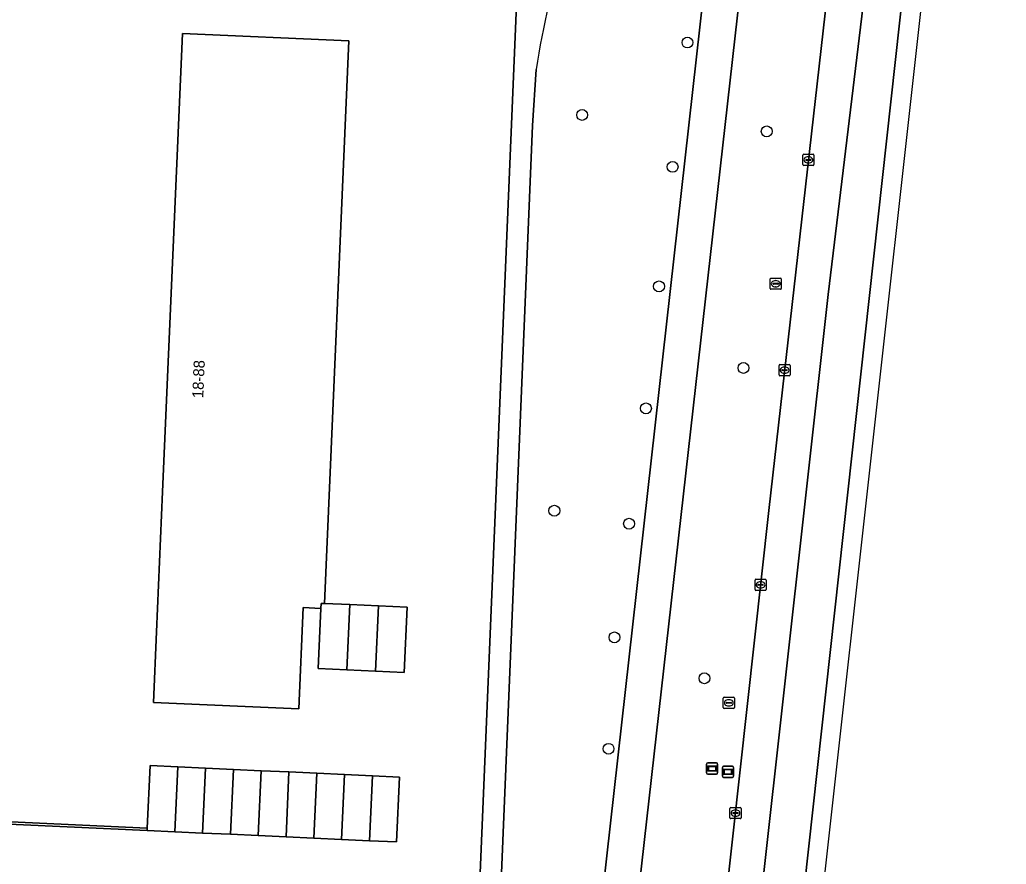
# Model space of a CAD drawing. Extents: x 161354 to 162026, y 386504 to 387460.
# Drawn here: x 161895 to 161983.7, y 386903.7 to 386979.6 of the extents above; entities that cross this region are included whole.
import ezdxf

# ---------------------------------------------------------------- set-up
doc = ezdxf.new("R2010")
doc.units = 0
for name, color, linetype in [('IMGEO_Berm_groen', 7, 'Continuous'), ('IMGEO_Boom', 7, 'Continuous'), ('IMGEO_Erf', 7, 'Continuous'), ('IMGEO_Fietspad_gesloten', 7, 'Continuous'), ('IMGEO_Kolk', 7, 'Continuous'), ('IMGEO_Loofbos', 7, 'Continuous'), ('IMGEO_Muur', 7, 'Continuous'), ('IMGEO_Pand', 7, 'Continuous'), ('IMGEO_Pand_nummerreeks', 7, 'Continuous'), ('IMGEO_Rijbaan_regionaal_gesloten', 7, 'Continuous'), ('IMGEO_Rioolput', 7, 'Continuous'), ('IMGEO_Voetpad_halfverhard', 7, 'Continuous'), ('IMGEO_Wegwijzer', 7, 'Continuous')]:
    doc.layers.add(name, color=color, linetype=linetype)

msp = doc.modelspace()

# ---------------------------------------------------------------- linework, layer by layer
at = {"layer": 'IMGEO_Berm_groen'}
for points in [[(161967.257, 387050.915), (161961.639, 387000), (161960.38, 386987.709), (161938.796, 386796.287), (161936.822, 386778.776), (161933.448, 386750), (161933.024, 386747.211), (161931.111, 386738.486), (161920.088, 386699.556), (161913.466, 386677.408), (161909.577, 386666.417)], [(161931.854, 386730.957), (161936.419, 386750), (161939.69, 386764.511), (161941.551, 386773.496), (161945.484, 386795.546), (161945.681, 386796.648), (161949.337, 386819.995), (161954.584, 386865.29), (161962.329, 386935.471), (161969.651, 387000), (161975.237, 387050.12)]]:
    msp.add_lwpolyline(points, dxfattribs=at)
at = {"layer": 'IMGEO_Boom'}
for centre in [(161955.019, 386977.518), (161945.55, 386971.009), (161962.142, 386969.533), (161953.686, 386966.346), (161952.46, 386955.604), (161960.052, 386948.28), (161951.282, 386944.646), (161943.052, 386935.456), (161949.767, 386934.285), (161948.456, 386924.068), (161956.544, 386920.397), (161947.924, 386914.063)]:
    msp.add_circle(centre, 0.489, dxfattribs=at)
at = {"layer": 'IMGEO_Erf'}
for points in [[(161885.264, 386901.684), (161936.238, 386899.338), (161940.02, 386989.533), (161894.944, 386991.428)], [(161891.578, 386907.611), (161906.455, 386906.926), (161906.714, 386912.556), (161909.211, 386912.441), (161911.709, 386912.326), (161914.206, 386912.211), (161916.703, 386912.097), (161919.201, 386911.982), (161921.698, 386911.867), (161924.196, 386911.752), (161926.693, 386911.638), (161929.146, 386911.525), (161928.878, 386905.694), (161926.425, 386905.807), (161923.928, 386905.922), (161921.43, 386906.037), (161918.933, 386906.152), (161916.435, 386906.267), (161913.938, 386906.382), (161911.441, 386906.496), (161908.943, 386906.611), (161906.446, 386906.726), (161891.37, 386907.42)]]:
    msp.add_lwpolyline(points, dxfattribs=at)
msp.add_lwpolyline([(161924.585, 386977.677), (161922.388, 386927.113), (161924.662, 386927.014), (161927.238, 386926.902), (161929.812, 386926.79), (161929.558, 386920.928), (161926.983, 386921.04), (161924.407, 386921.152), (161921.832, 386921.264), (161922.067, 386926.675), (161920.488, 386926.744), (161920.093, 386917.65), (161907.022, 386918.218), (161907.298, 386924.565), (161907.845, 386937.154), (161909.635, 386978.326)], close=True, dxfattribs=at)
at = {"layer": 'IMGEO_Fietspad_gesloten'}
for points in [[(161964.191, 387051.221), (161958.492, 387000), (161935.661, 386796.635)], [(161938.796, 386796.287), (161960.38, 386987.709), (161961.639, 387000), (161967.257, 387050.915)]]:
    msp.add_lwpolyline(points, dxfattribs=at)
at = {"layer": 'IMGEO_Kolk'}
for p, q in [((161965.388, 386966.547), (161965.388, 386967.399)), ((161965.463, 386967.473), (161966.315, 386967.473)), ((161966.389, 386967.399), (161966.389, 386966.547)), ((161966.315, 386966.473), (161965.463, 386966.473)), ((161965.647, 386966.967), (161965.647, 386966.979)), ((161966.085, 386966.93), (161965.687, 386966.93)), ((161965.69, 386967.016), (161966.088, 386967.016)), ((161965.899, 386966.693), (161965.874, 386966.693)), ((161965.876, 386967.253), (161965.901, 386967.253)), ((161966.131, 386966.979), (161966.131, 386966.967)), ((161963.246, 386947.653), (161963.246, 386948.505)), ((161963.321, 386948.579), (161964.173, 386948.579)), ((161963.505, 386948.073), (161963.505, 386948.085)), ((161963.943, 386948.036), (161963.545, 386948.036)), ((161963.548, 386948.122), (161963.946, 386948.122)), ((161963.734, 386948.359), (161963.759, 386948.359)), ((161963.989, 386948.085), (161963.989, 386948.073)), ((161964.247, 386948.505), (161964.247, 386947.653)), ((161964.173, 386947.579), (161963.321, 386947.579)), ((161963.757, 386947.799), (161963.732, 386947.799)), ((161961.094, 386928.366), (161961.094, 386929.218)), ((161961.169, 386929.292), (161962.021, 386929.292)), ((161962.095, 386929.218), (161962.095, 386928.366)), ((161961.353, 386928.786), (161961.353, 386928.798)), ((161961.791, 386928.749), (161961.393, 386928.749)), ((161961.396, 386928.835), (161961.794, 386928.835)), ((161961.605, 386928.512), (161961.58, 386928.512)), ((161961.582, 386929.072), (161961.607, 386929.072)), ((161961.837, 386928.798), (161961.837, 386928.786)), ((161962.021, 386928.292), (161961.169, 386928.292)), ((161958.911, 386908.786), (161959.763, 386908.786)), ((161958.836, 386907.86), (161958.836, 386908.712)), ((161959.095, 386908.28), (161959.095, 386908.292)), ((161959.533, 386908.243), (161959.135, 386908.243)), ((161959.138, 386908.329), (161959.536, 386908.329)), ((161959.347, 386908.006), (161959.322, 386908.006)), ((161959.324, 386908.566), (161959.349, 386908.566)), ((161959.579, 386908.292), (161959.579, 386908.28)), ((161959.837, 386908.712), (161959.837, 386907.86)), ((161959.763, 386907.786), (161958.911, 386907.786))]:
    msp.add_line(p, q, dxfattribs=at)
for points in [[(161965.388, 386966.547), (161965.388, 386967.399)], [(161965.463, 386967.473), (161966.315, 386967.473)], [(161966.389, 386967.399), (161966.389, 386966.547)], [(161966.315, 386966.473), (161965.463, 386966.473)], [(161963.246, 386947.653), (161963.246, 386948.505)], [(161963.321, 386948.579), (161964.173, 386948.579)], [(161964.247, 386948.505), (161964.247, 386947.653)], [(161964.173, 386947.579), (161963.321, 386947.579)], [(161961.094, 386928.366), (161961.094, 386929.218)], [(161961.169, 386929.292), (161962.021, 386929.292)], [(161962.095, 386929.218), (161962.095, 386928.366)], [(161962.021, 386928.292), (161961.169, 386928.292)], [(161958.911, 386908.786), (161959.763, 386908.786)], [(161958.836, 386907.86), (161958.836, 386908.712)], [(161959.837, 386908.712), (161959.837, 386907.86)], [(161959.763, 386907.786), (161958.911, 386907.786)]]:
    msp.add_lwpolyline(points, dxfattribs=at)
for centre, radius, start, end in [((161965.465, 386967.397), 0.0765, 91.55205, 178.44795), ((161965.465, 386967.397), 0.0765, 91.55205, 178.44795), ((161966.313, 386967.397), 0.0765, 1.55205, 88.44795), ((161966.313, 386967.397), 0.0765, 1.55205, 88.44795), ((161965.465, 386966.549), 0.0765, 181.55205, 268.44795), ((161965.465, 386966.549), 0.0765, 181.55205, 268.44795), ((161965.687, 386966.976), 0.0403, 85.87752, 175.75265), ((161965.684, 386966.966), 0.0366, 178.93798, 274.71019), ((161966.088, 386966.973), 0.043, 264.86636, 352.45326), ((161966.092, 386966.978), 0.0386, 1.73085, 96.63898), ((161966.313, 386966.549), 0.0765, 271.55205, 358.44795), ((161966.313, 386966.549), 0.0765, 271.55205, 358.44795), ((161963.323, 386948.503), 0.0765, 91.55205, 178.44795), ((161963.323, 386948.503), 0.0765, 91.55205, 178.44795), ((161963.545, 386948.082), 0.0403, 85.87752, 175.75265), ((161963.542, 386948.072), 0.0366, 178.93798, 274.71019), ((161963.946, 386948.079), 0.043, 264.86636, 352.45326), ((161963.95, 386948.084), 0.0386, 1.73085, 96.63898), ((161964.171, 386948.503), 0.0765, 1.55205, 88.44795), ((161964.171, 386948.503), 0.0765, 1.55205, 88.44795), ((161963.323, 386947.655), 0.0765, 181.55205, 268.44795), ((161963.323, 386947.655), 0.0765, 181.55205, 268.44795), ((161964.171, 386947.655), 0.0765, 271.55205, 358.44795), ((161964.171, 386947.655), 0.0765, 271.55205, 358.44795), ((161961.171, 386929.216), 0.0765, 91.55205, 178.44795), ((161961.171, 386929.216), 0.0765, 91.55205, 178.44795), ((161962.019, 386929.216), 0.0765, 1.55205, 88.44795), ((161962.019, 386929.216), 0.0765, 1.55205, 88.44795), ((161961.171, 386928.368), 0.0765, 181.55205, 268.44795), ((161961.171, 386928.368), 0.0765, 181.55205, 268.44795), ((161961.393, 386928.795), 0.0403, 85.87752, 175.75265), ((161961.39, 386928.785), 0.0366, 178.93798, 274.71019), ((161961.794, 386928.792), 0.043, 264.86636, 352.45326), ((161961.798, 386928.797), 0.0386, 1.73085, 96.63898), ((161962.019, 386928.368), 0.0765, 271.55205, 358.44795), ((161962.019, 386928.368), 0.0765, 271.55205, 358.44795), ((161958.913, 386908.71), 0.0765, 91.55205, 178.44795), ((161958.913, 386908.71), 0.0765, 91.55205, 178.44795), ((161959.761, 386908.71), 0.0765, 1.55205, 88.44795), ((161959.761, 386908.71), 0.0765, 1.55205, 88.44795), ((161959.135, 386908.289), 0.0403, 85.87752, 175.75265), ((161959.132, 386908.279), 0.0366, 178.93798, 274.71019), ((161959.536, 386908.286), 0.043, 264.86636, 352.45326), ((161959.54, 386908.291), 0.0386, 1.73085, 96.63898), ((161958.913, 386907.862), 0.0765, 181.55205, 268.44795), ((161958.913, 386907.862), 0.0765, 181.55205, 268.44795), ((161959.761, 386907.862), 0.0765, 271.55205, 358.44795), ((161959.761, 386907.862), 0.0765, 271.55205, 358.44795)]:
    msp.add_arc(centre, radius, start, end, dxfattribs=at)
for centre, major_axis, ratio, start_param, end_param in [((161965.875, 386966.973), (-0.387, 0.002), 0.722429, 4.712389, 7.853982), ((161965.9, 386966.973), (-0.39, 0.002), 0.717154, 1.570796, 4.712389), ((161963.733, 386948.079), (-0.387, 0.002), 0.722429, 4.712389, 7.853982), ((161963.758, 386948.079), (-0.39, 0.002), 0.717154, 1.570796, 4.712389), ((161961.581, 386928.792), (-0.387, 0.002), 0.722429, 4.712389, 7.853982), ((161961.606, 386928.792), (-0.39, 0.002), 0.717154, 1.570796, 4.712389), ((161959.323, 386908.286), (-0.387, 0.002), 0.722429, 4.712389, 7.853982), ((161959.348, 386908.286), (-0.39, 0.002), 0.717154, 1.570796, 4.712389)]:
    msp.add_ellipse(centre, major_axis=major_axis, ratio=ratio, start_param=start_param, end_param=end_param, dxfattribs=at)
at = {"layer": 'IMGEO_Loofbos'}
for points in [[(161913.776, 386748.036), (161911.767, 386689.472), (161913.777, 386689.388), (161921.99, 386717.644), (161927.704, 386738.292), (161930.041, 386748.73), (161930.197, 386750), (161932.945, 386772.439), (161935.661, 386796.635), (161958.492, 387000)], [(161941.407, 386975.097), (161941.082, 386970.072), (161938.146, 386899.309), (161937.723, 386895.33)]]:
    msp.add_lwpolyline(points, dxfattribs=at)
msp.add_arc((162043.236, 386958.619), 103.153, 157.58635, 170.80783, dxfattribs=at)
at = {"layer": 'IMGEO_Muur'}
msp.add_lwpolyline([(161891.965, 386921.204), (161891.37, 386907.42), (161906.446, 386906.726), (161906.455, 386906.926), (161891.578, 386907.611), (161892.338, 386925.195), (161892.138, 386925.204)], close=True, dxfattribs=at)
at = {"layer": 'IMGEO_Pand'}
for points in [[(161907.022, 386918.218), (161920.093, 386917.65), (161920.488, 386926.744), (161922.067, 386926.675), (161922.085, 386927.13), (161922.388, 386927.113), (161924.585, 386977.677), (161909.635, 386978.326), (161907.845, 386937.154), (161907.298, 386924.565)], [(161924.662, 386927.014), (161922.388, 386927.113), (161922.085, 386927.13), (161922.067, 386926.675), (161921.832, 386921.264), (161924.407, 386921.152)], [(161927.238, 386926.902), (161924.662, 386927.014), (161924.407, 386921.152), (161926.983, 386921.04)], [(161926.983, 386921.04), (161929.558, 386920.928), (161929.812, 386926.79), (161927.238, 386926.902)], [(161909.211, 386912.441), (161906.714, 386912.556), (161906.455, 386906.926), (161906.446, 386906.726), (161908.943, 386906.611)], [(161911.709, 386912.326), (161909.211, 386912.441), (161908.943, 386906.611), (161911.441, 386906.496)], [(161914.206, 386912.211), (161911.709, 386912.326), (161911.441, 386906.496), (161913.938, 386906.382)], [(161916.703, 386912.097), (161914.206, 386912.211), (161913.938, 386906.382), (161916.435, 386906.267)], [(161919.201, 386911.982), (161916.703, 386912.097), (161916.435, 386906.267), (161918.933, 386906.152)], [(161921.698, 386911.867), (161919.201, 386911.982), (161918.933, 386906.152), (161921.43, 386906.037)], [(161924.196, 386911.752), (161921.698, 386911.867), (161921.43, 386906.037), (161923.928, 386905.922)], [(161926.693, 386911.638), (161924.196, 386911.752), (161923.928, 386905.922), (161926.425, 386905.807)], [(161929.146, 386911.525), (161926.693, 386911.638), (161926.425, 386905.807), (161928.878, 386905.694)]]:
    msp.add_lwpolyline(points, close=True, dxfattribs=at)
at = {"layer": 'IMGEO_Rijbaan_regionaal_gesloten'}
for points in [[(161953.318, 386794.679), (161962.379, 386873.244), (161976.049, 386997.238), (161981.984, 387049.448), (161978.469, 387049.798), (161974.354, 387011.236), (161973.137, 387000.209), (161967.661, 386954.866), (161949.872, 386795.06), (161946.557, 386765.215), (161942.589, 386729.489), (161942.439, 386728.019), (161926.424, 386570.316), (161923.246, 386535.823), (161922.934, 386532.145), (161926.119, 386532.024), (161929.934, 386573.912), (161932.687, 386601.55), (161933.498, 386609.431), (161933.982, 386612.625), (161940.783, 386677.087)], [(161978.469, 387049.798), (161975.237, 387050.12), (161969.651, 387000), (161962.329, 386935.471), (161954.584, 386865.29), (161949.337, 386819.995), (161945.681, 386796.648), (161945.484, 386795.546), (161946.236, 386795.463), (161949.151, 386795.14), (161949.872, 386795.06), (161967.661, 386954.866), (161973.137, 387000.209), (161974.354, 387011.236)], [(161928.749, 386531.924), (161935.094, 386600.16), (161938.388, 386635.586), (161940.62, 386659.585), (161959.612, 386832.977), (161983.673, 387049.28), (161981.984, 387049.448), (161976.049, 386997.238), (161962.379, 386873.244), (161953.318, 386794.679), (161940.783, 386677.087), (161933.982, 386612.625), (161933.498, 386609.431), (161932.687, 386601.55), (161929.934, 386573.912), (161926.119, 386532.024)]]:
    msp.add_lwpolyline(points, close=True, dxfattribs=at)
at = {"layer": 'IMGEO_Rioolput'}
for p, q in [((161962.449, 386955.422), (161962.449, 386956.274)), ((161962.524, 386956.348), (161963.376, 386956.348)), ((161962.708, 386955.842), (161962.708, 386955.854)), ((161963.146, 386955.805), (161962.748, 386955.805)), ((161962.751, 386955.891), (161963.149, 386955.891)), ((161962.937, 386956.128), (161962.962, 386956.128)), ((161963.192, 386955.854), (161963.192, 386955.842)), ((161963.45, 386956.274), (161963.45, 386955.422)), ((161963.376, 386955.348), (161962.524, 386955.348)), ((161962.96, 386955.568), (161962.935, 386955.568)), ((161958.235, 386917.767), (161958.235, 386918.619)), ((161958.31, 386918.693), (161959.162, 386918.693)), ((161959.236, 386918.619), (161959.236, 386917.767)), ((161959.162, 386917.693), (161958.31, 386917.693)), ((161958.494, 386918.187), (161958.494, 386918.199)), ((161958.932, 386918.15), (161958.534, 386918.15)), ((161958.537, 386918.236), (161958.935, 386918.236)), ((161958.746, 386917.913), (161958.721, 386917.913)), ((161958.723, 386918.473), (161958.748, 386918.473)), ((161958.978, 386918.199), (161958.978, 386918.187))]:
    msp.add_line(p, q, dxfattribs=at)
for points in [[(161962.449, 386955.422), (161962.449, 386956.274)], [(161962.524, 386956.348), (161963.376, 386956.348)], [(161963.45, 386956.274), (161963.45, 386955.422)], [(161963.376, 386955.348), (161962.524, 386955.348)], [(161958.235, 386917.767), (161958.235, 386918.619)], [(161958.31, 386918.693), (161959.162, 386918.693)], [(161959.236, 386918.619), (161959.236, 386917.767)], [(161959.162, 386917.693), (161958.31, 386917.693)]]:
    msp.add_lwpolyline(points, dxfattribs=at)
for centre, radius, start, end in [((161962.526, 386956.272), 0.0765, 91.55205, 178.44795), ((161962.526, 386956.272), 0.0765, 91.55205, 178.44795), ((161962.748, 386955.851), 0.0403, 85.87752, 175.75265), ((161962.745, 386955.841), 0.0366, 178.93798, 274.71019), ((161963.149, 386955.848), 0.043, 264.86636, 352.45326), ((161963.153, 386955.853), 0.0386, 1.73085, 96.63898), ((161963.374, 386956.272), 0.0765, 1.55205, 88.44795), ((161963.374, 386956.272), 0.0765, 1.55205, 88.44795), ((161962.526, 386955.424), 0.0765, 181.55205, 268.44795), ((161962.526, 386955.424), 0.0765, 181.55205, 268.44795), ((161963.374, 386955.424), 0.0765, 271.55205, 358.44795), ((161963.374, 386955.424), 0.0765, 271.55205, 358.44795), ((161958.312, 386918.617), 0.0765, 91.55205, 178.44795), ((161958.312, 386918.617), 0.0765, 91.55205, 178.44795), ((161959.16, 386918.617), 0.0765, 1.55205, 88.44795), ((161959.16, 386918.617), 0.0765, 1.55205, 88.44795), ((161958.312, 386917.769), 0.0765, 181.55205, 268.44795), ((161958.312, 386917.769), 0.0765, 181.55205, 268.44795), ((161958.534, 386918.196), 0.0403, 85.87752, 175.75265), ((161958.531, 386918.186), 0.0366, 178.93798, 274.71019), ((161958.935, 386918.193), 0.043, 264.86636, 352.45326), ((161958.939, 386918.198), 0.0386, 1.73085, 96.63898), ((161959.16, 386917.769), 0.0765, 271.55205, 358.44795), ((161959.16, 386917.769), 0.0765, 271.55205, 358.44795)]:
    msp.add_arc(centre, radius, start, end, dxfattribs=at)
for centre, major_axis, ratio, start_param, end_param in [((161962.936, 386955.848), (-0.387, 0.002), 0.722429, 4.712389, 7.853982), ((161962.961, 386955.848), (-0.39, 0.002), 0.717154, 1.570796, 4.712389), ((161958.722, 386918.193), (-0.387, 0.002), 0.722429, 4.712389, 7.853982), ((161958.747, 386918.193), (-0.39, 0.002), 0.717154, 1.570796, 4.712389)]:
    msp.add_ellipse(centre, major_axis=major_axis, ratio=ratio, start_param=start_param, end_param=end_param, dxfattribs=at)
at = {"layer": 'IMGEO_Voetpad_halfverhard'}
for points in [[(161949.829, 387052.652), (161948.584, 387020.063), (161948.284, 387012.203), (161947.779, 387006.274), (161946.435, 387000), (161946.053, 386998.219), (161946.029, 386998.119), (161945.843, 386997.496), (161945.603, 386996.892), (161945.309, 386996.312), (161944.965, 386995.76), (161944.573, 386995.242), (161944.136, 386994.761), (161943.658, 386994.32), (161943.143, 386993.924), (161942.594, 386993.576), (161942.016, 386993.278), (161941.414, 386993.033), (161940.793, 386992.842), (161940.157, 386992.708), (161940.02, 386989.533), (161936.238, 386899.338)], [(161941.082, 386970.072), (161941.407, 386975.097)], [(161937.723, 386895.33), (161938.146, 386899.309), (161941.082, 386970.072)]]:
    msp.add_lwpolyline(points, dxfattribs=at)
msp.add_arc((162043.236, 386958.619), 103.153, 157.58635, 170.80783, dxfattribs=at)
at = {"layer": 'IMGEO_Wegwijzer'}
for p, q in [((161956.742, 386911.89), (161956.742, 386912.69)), ((161956.742, 386912.69), (161956.742, 386911.89)), ((161956.842, 386912.79), (161957.632, 386912.79)), ((161957.632, 386912.79), (161956.842, 386912.79)), ((161957.732, 386912.69), (161957.732, 386911.89)), ((161957.732, 386911.89), (161957.732, 386912.69)), ((161958.161, 386911.595), (161958.161, 386912.395)), ((161958.161, 386912.395), (161958.161, 386911.595)), ((161958.261, 386912.495), (161959.051, 386912.495)), ((161959.051, 386912.495), (161958.261, 386912.495)), ((161959.151, 386912.395), (161959.151, 386911.595)), ((161959.151, 386911.595), (161959.151, 386912.395)), ((161957.632, 386911.79), (161956.842, 386911.79)), ((161956.842, 386911.79), (161957.632, 386911.79)), ((161959.051, 386911.495), (161958.261, 386911.495)), ((161958.261, 386911.495), (161959.051, 386911.495))]:
    msp.add_line(p, q, dxfattribs=at)
for points in [[(161956.843, 386912.522), (161957.631, 386912.522), (161957.631, 386912.058), (161956.843, 386912.058), (161956.843, 386912.522)], [(161956.908, 386912.457), (161956.908, 386912.123), (161957.566, 386912.123), (161957.566, 386912.457), (161956.908, 386912.457)], [(161958.262, 386912.227), (161959.05, 386912.227), (161959.05, 386911.763), (161958.262, 386911.763), (161958.262, 386912.227)], [(161958.327, 386912.162), (161958.327, 386911.828), (161958.985, 386911.828), (161958.985, 386912.162), (161958.327, 386912.162)]]:
    msp.add_lwpolyline(points, dxfattribs=at)
for centre, start, end in [((161956.842, 386912.69), 90, 180), ((161956.842, 386912.69), 90, 180), ((161957.632, 386912.69), 0, 90), ((161957.632, 386912.69), 360, 90), ((161958.261, 386912.395), 90, 180), ((161958.261, 386912.395), 90, 180), ((161959.051, 386912.395), 0, 90), ((161959.051, 386912.395), 360, 90), ((161956.842, 386911.89), 180, 270), ((161956.842, 386911.89), 180, 270), ((161957.632, 386911.89), 270, 0), ((161957.632, 386911.89), 270, 0), ((161958.261, 386911.595), 180, 270), ((161958.261, 386911.595), 180, 270), ((161959.051, 386911.595), 270, 0), ((161959.051, 386911.595), 270, 0)]:
    msp.add_arc(centre, 0.1, start, end, dxfattribs=at)

# ---------------------------------------------------------------- texts
at = {"layer": 'IMGEO_Pand_nummerreeks'}
msp.add_text('18-88', height=1, rotation=87.51082, dxfattribs=at).set_placement((161911.493, 386945.55))

doc.saveas('drawing.dxf')
